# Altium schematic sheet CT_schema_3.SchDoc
size 313 x 185 mm
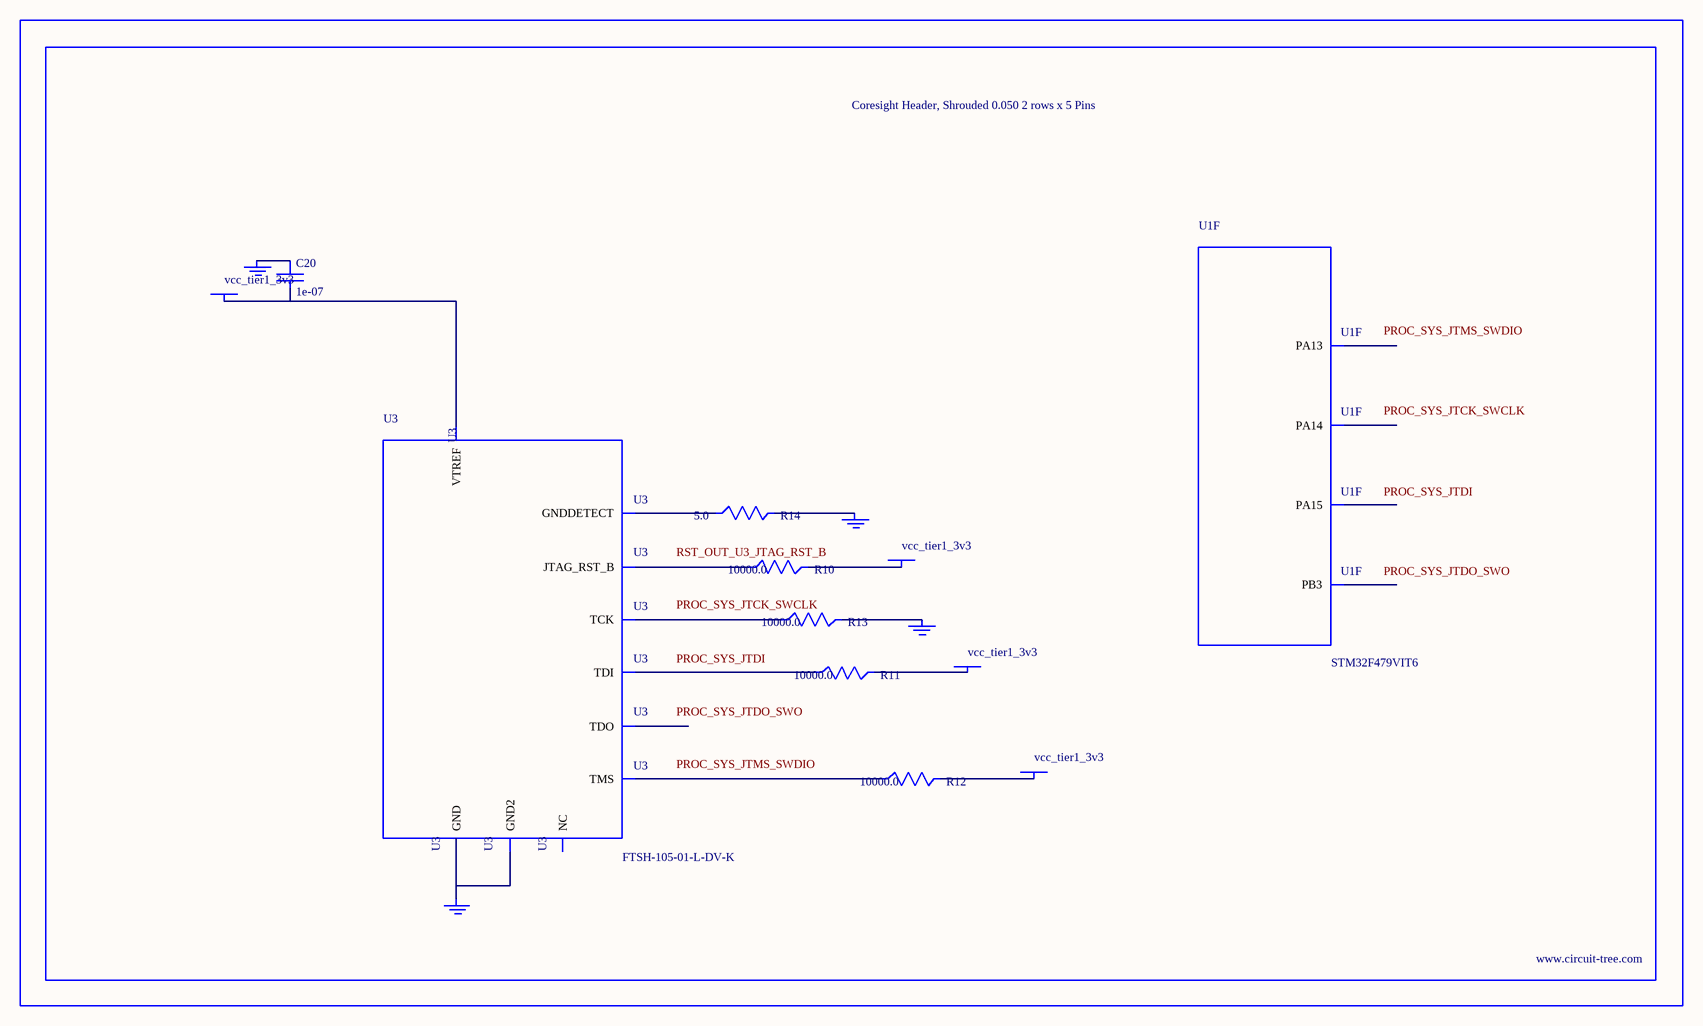
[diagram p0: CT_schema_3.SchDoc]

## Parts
BORDER2  (no value)
C20  1e-07  [C0402]
GND_INSTANCE_2_0  (no value)
GND_INSTANCE_2_1  (no value)
GND_INSTANCE_2_2  (no value)
GND_INSTANCE_2_3  (no value)
POWER_INSTANCE_2_0  vcc_tier1_3v3
POWER_INSTANCE_2_1  vcc_tier1_3v3
POWER_INSTANCE_2_2  vcc_tier1_3v3
POWER_INSTANCE_2_3  vcc_tier1_3v3
R10  10000.0  [R0603]
R11  10000.0  [R0603]
R12  10000.0  [R0603]
R13  10000.0  [R0603]
R14  5.0  [R0603]
U1  STM32F479VIT6  [LQFP100]  (part F of 9)
U3  FTSH-105-01-L-DV-K  [SAMTEC_FTSH-105-01-L-DV-K]

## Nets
NetC20_1: C20.1 GND_INSTANCE_2_0.0(GND)
NetC20_2: C20.2 POWER_INSTANCE_2_0.0(PWR) U3.1(VTREF)
NetGND_INSTANCE_2_1_0: GND_INSTANCE_2_1.0(GND) R13.2
NetGND_INSTANCE_2_2_0: GND_INSTANCE_2_2.0(GND) R14.2
NetGND_INSTANCE_2_3_0: GND_INSTANCE_2_3.0(GND) U3.3(GND) U3.5(GND2)
NetPOWER_INSTANCE_2_1_0: POWER_INSTANCE_2_1.0(PWR) R12.2
NetPOWER_INSTANCE_2_2_0: POWER_INSTANCE_2_2.0(PWR) R11.2
NetPOWER_INSTANCE_2_3_0: POWER_INSTANCE_2_3.0(PWR) R10.2
NetR10_1: R10.1 U3.10(JTAG_RST_B)
NetR11_1: R11.1 U3.8(TDI)
NetR12_1: R12.1 U3.2(TMS)
NetR13_1: R13.1 U3.4(TCK)
NetR14_1: R14.1 U3.9(GNDDETECT)

Not connected (* = marked no-connect by the designer): U1 75(PA13) 79(PA14) 80(PA15) 92(PB3); U3 6(TDO) 7(NC)

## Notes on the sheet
- Labels drawn without touching a wire or pin: PROC_SYS_JTCK_SWCLK, PROC_SYS_JTDI, PROC_SYS_JTDO_SWO, PROC_SYS_JTMS_SWDIO, RST_OUT_U3_JTAG_RST_B

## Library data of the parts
BORDER2 = BORDER_PAGE2
C20 = C0402C104K3RACTU
GND_INSTANCE_2_0-GND_INSTANCE_2_3 = GND
POWER_INSTANCE_2_0-POWER_INSTANCE_2_3 = PWR
R10-R13 = RC0603JR-0710KL
R14 = ERJ-3GEYJ5R1V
